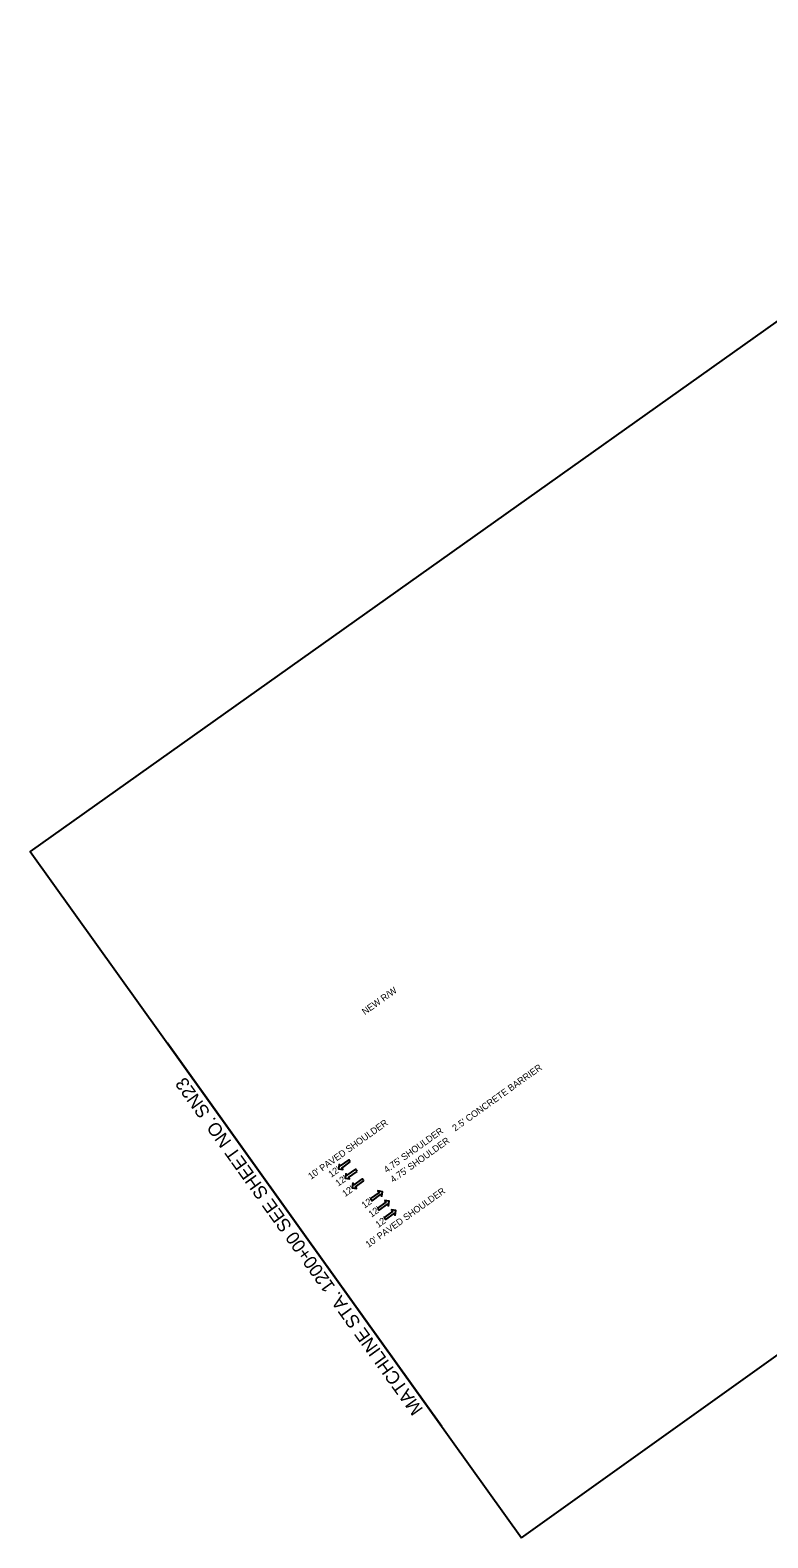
# Model space of a CAD drawing. Extents: x 1769713 to 1771399, y 1177155 to 1178792.
# Drawn here: x 1769713 to 1770495, y 1177155 to 1178754 of the extents above; entities that cross this region are included whole.
import ezdxf

# ---------------------------------------------------------------- set-up
doc = ezdxf.new("R2010")
doc.units = 0
for name, color, linetype in [('RD_HC_Data', 7, 'Continuous'), ('RD_PD_GR', 7, 'Continuous'), ('RD_PD_MedBWall', 7, 'Continuous'), ('RD_QTY_GR', 7, 'Continuous'), ('RD_SHT_MatchLine', 7, 'Continuous')]:
    doc.layers.add(name, color=color, linetype=linetype)

# ---------------------------------------------------------------- blocks, each defined once
blk = doc.blocks.new('SARRW2')
at = {"layer": 'RD_PD_GR'}
blk.add_lwpolyline([(-12, 1.2), (-12, -1.2), (-2.8, -1.2), (-2.8, -2.8), (0, 0), (-2.8, 2.8), (-2.8, 1.2)], close=True, dxfattribs=at)

msp = doc.modelspace()

# ---------------------------------------------------------------- linework, layer by layer
at = {"layer": 'RD_HC_Data'}
msp.add_lwpolyline([(1770233.7, 1177155.2), (1770800.5, 1177559.9), (1771027.1, 1177721.7), (1771013.4, 1177780.4), (1771398.9, 1178099.1), (1771333.7, 1178192), (1771094.5, 1178533.3), (1770940, 1178753.7), (1769712.5, 1177882.8), (1769897.9, 1177624), (1770003.7, 1177476.3), (1770123.1, 1177309.6)], close=True, dxfattribs=at)
at = {"layer": 'RD_SHT_MatchLine'}
msp.add_lwpolyline([(1770149.3, 1177273.1), (1770003.7, 1177476.3), (1769858.1, 1177679.5)], dxfattribs=at)

# ---------------------------------------------------------------- block references
at = {"layer": 'RD_PD_GR', "xscale": 1.1999999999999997}
for p, yscale, rotation in [((1770039.6, 1177546.5), 1.2000000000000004, -144.38650217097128), ((1770046.7, 1177536.5), 1.2000000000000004, -144.38650217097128), ((1770054, 1177526.4), 1.2000000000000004, -144.38650217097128), ((1770086.2, 1177522.2), 1.2, 35.61349782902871), ((1770093.5, 1177512), 1.2, 35.61349782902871), ((1770100.6, 1177502.1), 1.2, 35.61349782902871)]:
    msp.add_blockref('SARRW2', p, dxfattribs=dict(at, yscale=yscale, rotation=rotation))

# ---------------------------------------------------------------- texts
at = {"layer": 'RD_PD_MedBWall'}
for s, p in [("2.5' CONCRETE BARRIER", (1770163.4, 1177585.9)), ("10' PAVED SHOULDER", (1770010.5, 1177534.8)), ("4.75' SHOULDER", (1770090.8, 1177541.7)), ("4.75' SHOULDER", (1770097.6, 1177531.4)), ("12'", (1770032, 1177536.9)), ("12'", (1770039.4, 1177527.5)), ("12'", (1770046.7, 1177516.4)), ("12'", (1770067.2, 1177504.1)), ("10' PAVED SHOULDER", (1770071.4, 1177462.5)), ("12'", (1770074.6, 1177494.6)), ("12'", (1770081.9, 1177483.6))]:
    msp.add_text(s, height=7, rotation=35.6135, dxfattribs=at).set_placement(p)
at = {"layer": 'RD_QTY_GR'}
msp.add_text('NEW R/W', height=7, rotation=35.5257, dxfattribs=at).set_placement((1770067.6, 1177709.3))
at = {"layer": 'RD_SHT_MatchLine'}
msp.add_text('MATCHLINE STA. 1200+00 SEE SHEET NO. SN23', height=14, rotation=125.6135, dxfattribs=at).set_placement((1770129.9, 1177291.5))

doc.saveas('drawing.dxf')
